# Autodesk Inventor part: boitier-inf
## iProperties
Author: robert
Shininess: 20.0
Angle Display Precision: 2
Document Length Units: 11269
Document Angle Units: 11283
Document Time Units: 11279
Document Mass Units: 11290
Document Length Units Precision: 3
Document Angle Units Precision: 2
Compacted: True
PropertySet Name: _Private Model Information
Created: 2002-06
Part Number: boitier-inf
Material: Par défaut
Document SubType Name: Modélisation
Designer: robert
Control State: 0
Master: False
Checked Out: False
PropertySet Name: Design Tracking Control
Density: 0.0
Volumn: 0.0
Area: 0.0
PropertySet Name: Model Information
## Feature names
1. Extrusion1
2. Congé1 [Fillet]
3. Coque1
